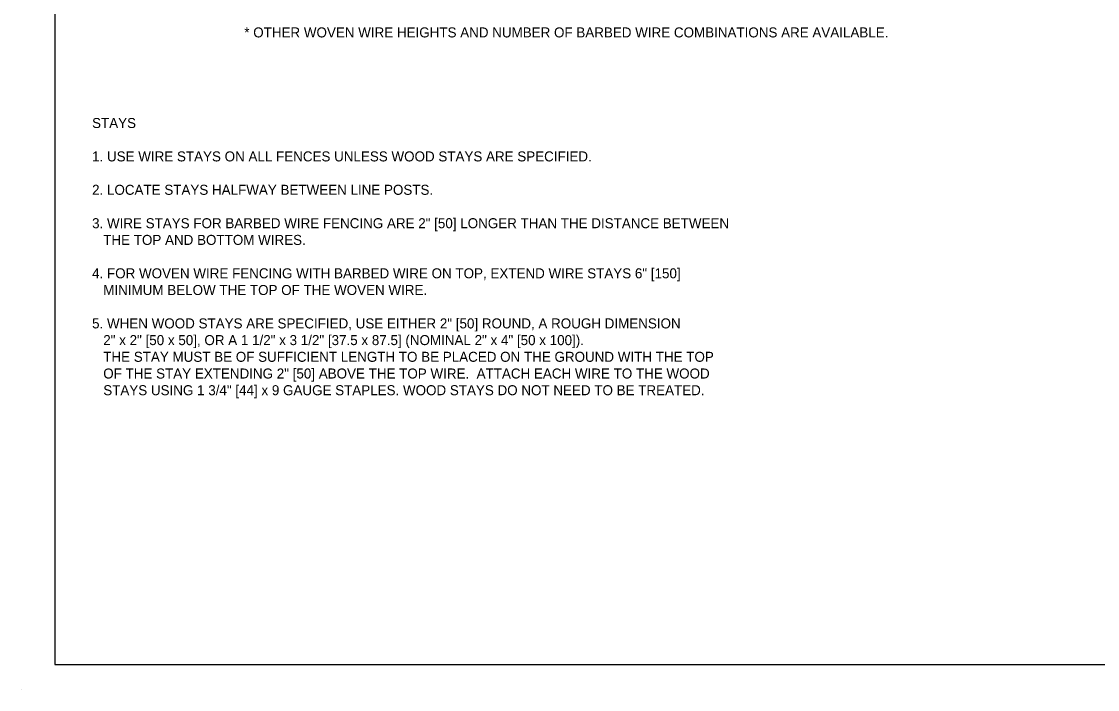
# Model space of a CAD drawing. Extents: x 49991.4 to 50021, y 49987.6 to 50011.4.
# Drawn here: x 50009.54 to 50015.98, y 49999.74 to 50003.74 of the extents above; entities that cross this region are included whole.
import ezdxf

# ---------------------------------------------------------------- set-up
doc = ezdxf.new("R2010")
doc.units = 0
doc.layers.add('Level 1', color=7, linetype='Continuous')
doc.layers.add('Level 2', color=7, linetype='Continuous')

msp = doc.modelspace()

# ---------------------------------------------------------------- linework, layer by layer
at = {"layer": 'Level 1'}
msp.add_line((50009.5374, 49999.7356), (50009.5374, 49999.7356), dxfattribs=at)
msp.add_line((50009.5374, 49999.7356), (50009.5374, 49999.7356), dxfattribs=at)
msp.add_lwpolyline([(50020.9378, 50008.1646), (50009.7374, 50008.1646), (50009.7374, 49999.8856), (50020.9378, 49999.8856)], close=True, dxfattribs=at)
msp.add_lwpolyline([(50020.9378, 50008.1646), (50009.7374, 50008.1646), (50009.7374, 49999.8856), (50020.9378, 49999.8856)], close=True, dxfattribs=at)

# ---------------------------------------------------------------- texts
at = {"layer": 'Level 2'}
for s, p in [('* OTHER WOVEN WIRE HEIGHTS AND NUMBER OF BARBED WIRE COMBINATIONS ARE AVAILABLE.', (50010.8711, 50003.6402)), ('STAYS', (50009.9599, 50003.0977)), ('1. USE WIRE STAYS ON ALL FENCES UNLESS WOOD STAYS ARE SPECIFIED.', (50009.9599, 50002.8977)), ('2. LOCATE STAYS HALFWAY BETWEEN LINE POSTS.', (50009.9599, 50002.6977)), ('3. WIRE STAYS FOR BARBED WIRE FENCING ARE 2" [50] LONGER THAN THE DISTANCE BETWEEN', (50009.9599, 50002.4977)), ('   THE TOP AND BOTTOM WIRES.', (50009.9599, 50002.3977)), ('4. FOR WOVEN WIRE FENCING WITH BARBED WIRE ON TOP, EXTEND WIRE STAYS 6" [150] ', (50009.9599, 50002.1977)), ('   MINIMUM BELOW THE TOP OF THE WOVEN WIRE.', (50009.9599, 50002.0977)), ('5. WHEN WOOD STAYS ARE SPECIFIED, USE EITHER 2" [50] ROUND, A ROUGH DIMENSION', (50009.9599, 50001.8977)), ('   2" x 2" [50 x 50], OR A 1 1/2" x 3 1/2" [37.5 x 87.5] (NOMINAL 2" x 4" [50 x 100]).', (50009.9599, 50001.7977)), ('   THE STAY MUST BE OF SUFFICIENT LENGTH TO BE PLACED ON THE GROUND WITH THE TOP', (50009.9599, 50001.6977)), ('   OF THE STAY EXTENDING 2" [50] ABOVE THE TOP WIRE.  ATTACH EACH WIRE TO THE WOOD', (50009.9599, 50001.5977)), ('   STAYS USING 1 3/4" [44] x 9 GAUGE STAPLES. WOOD STAYS DO NOT NEED TO BE TREATED.', (50009.9599, 50001.4977))]:
    msp.add_text(s, height=0.06, dxfattribs=at).set_placement(p)

doc.saveas('drawing.dxf')
